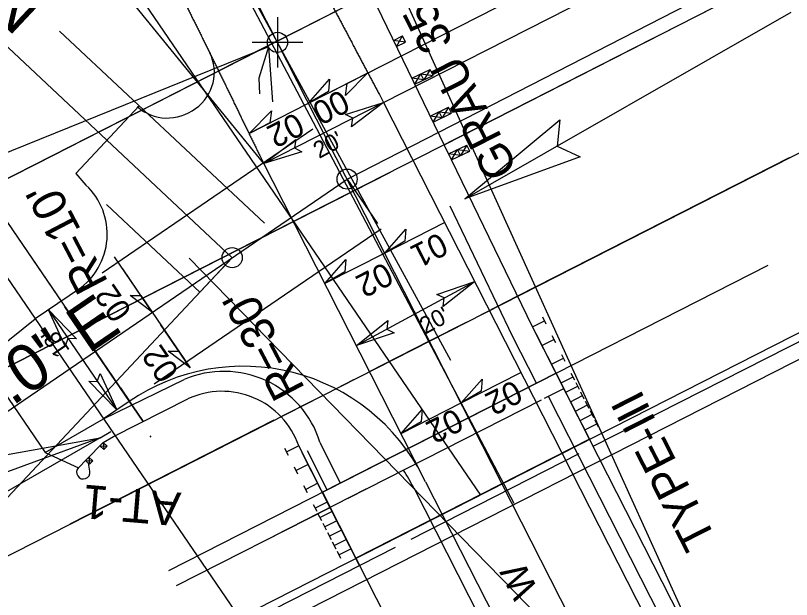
# Model space of a CAD drawing. Extents: x 557583 to 560285, y 513145 to 516544.
# Drawn here: x 559282.2 to 559397.5, y 515542.3 to 515629.1 of the extents above; entities that cross this region are included whole.
import ezdxf

# ---------------------------------------------------------------- set-up
doc = ezdxf.new("R2010")
doc.units = 0
for name, color, linetype in [('COGO Default Chain', 7, 'Continuous'), ('Exist Environmental Wetland Boundary', 7, 'Continuous'), ('Exist Environmental Wetland Boundary Cogo Point CELL', 7, 'Continuous'), ('Exist Hydro Jurisdictional Stream or Body of Water NEU Mitigable Cogo Comment', 7, 'Continuous'), ('Exist Hydro Jurisdictional Stream or Body of Water NEU Mitigable Cogo Elevation', 7, 'Continuous'), ('Exist Hydro Jurisdictional Stream or Body of Water NEU Mitigable Cogo Point CELL', 7, 'Continuous'), ('Exist Hydro Swamp or Marsh', 7, 'Continuous'), ('Prop Approach Slab', 7, 'Continuous'), ('Prop Dimension', 7, 'Continuous'), ('Prop DSN Text', 7, 'Continuous'), ('Prop EOT', 7, 'Continuous'), ('Prop Guardrail', 7, 'Continuous'), ('Prop Guardrail Anchor Unit CELL', 7, 'Continuous'), ('Prop Guardrail Shop Curved', 7, 'Continuous'), ('Prop Paved Shoulder', 7, 'Continuous'), ('Prop Roadway Bridge', 7, 'Continuous'), ('Prop SBG', 7, 'Continuous'), ('Prop Structure Anchor Unit CELL', 7, 'Continuous'), ('Prop Superelevation Label', 7, 'Continuous'), ('Prop Terminator CELL', 7, 'Continuous'), ('Scratch_Level_0', 7, 'Continuous'), ('Scratch_Level_1', 7, 'Continuous'), ('Scratch_Level_2', 7, 'Continuous'), ('Scratch_Level_3', 7, 'Continuous'), ('Scratch_Level_4', 7, 'Continuous'), ('Scratch_Level_6', 7, 'Continuous'), ('Scratch_Level_7', 7, 'Continuous'), ('Scratch_Level_8', 7, 'Continuous')]:
    doc.layers.add(name, color=color, linetype=linetype)

msp = doc.modelspace()

# ---------------------------------------------------------------- linework, layer by layer
at = {"layer": 'COGO Default Chain'}
for p, q in [((559321.14, 515628.83), (559321.14, 515621.33)), ((559324.89, 515625.08), (559317.39, 515625.08))]:
    msp.add_line(p, q, dxfattribs=at)
msp.add_arc((558429.99, 515171.37), 1000, 26.98193, 30.25241, dxfattribs=at)
at = {"layer": 'Exist Environmental Wetland Boundary'}
for p, q in [((559331.48, 515604.76), (559335.99, 515598.16)), ((559314.39, 515593.08), (559308.92, 515587.24))]:
    msp.add_line(p, q, dxfattribs=at)
at = {"layer": 'Exist Environmental Wetland Boundary Cogo Point CELL'}
for p, q in [((559331.48, 515604.76), (559390.68, 515635.1)), ((559319.8, 515624.4), (559235.59, 515590.45)), ((559313.36, 515591.99), (559124.03, 515390.09))]:
    msp.add_line(p, q, dxfattribs=at)
for centre in [(559321.14, 515625.08), (559321.14, 515625.08), (559331.48, 515604.76), (559331.48, 515604.76), (559314.39, 515593.08)]:
    msp.add_circle(centre, 1.5, dxfattribs=at)
at = {"layer": 'Exist Hydro Jurisdictional Stream or Body of Water NEU Mitigable Cogo Elevation'}
for p, q in [((559314.39, 515593.08), (559222.63, 515679.13)), ((559379.56, 515510.32), (559321.14, 515625.08)), ((559211.5, 515522.74), (559331.48, 515604.76))]:
    msp.add_line(p, q, dxfattribs=at)
msp.add_arc((558429.99, 515171.37), 1000, 26.98193, 30.25241, dxfattribs=at)
at = {"layer": 'Exist Hydro Jurisdictional Stream or Body of Water NEU Mitigable Cogo Point CELL'}
for p, q in [((559325.73, 515616.05), (559334.57, 515620.55)), ((559316.9, 515611.55), (559325.73, 515616.05)), ((559345.99, 515598.31), (559337.07, 515593.77)), ((559337.07, 515593.77), (559328.16, 515589.23)), ((559302.52, 515584.96), (559298.12, 515591.4)), ((559308.16, 515576.71), (559303.76, 515583.15)), ((559348.42, 515571.49), (559357.33, 515576.03)), ((559339.51, 515566.95), (559348.42, 515571.49))]:
    msp.add_line(p, q, dxfattribs=at)
for points in [[(559334.57, 515620.55), (559331.24, 515617.17), (559331.48, 515618.97)], [(559325.73, 515616.05), (559328.86, 515619.61), (559328.73, 515617.8)], [(559316.9, 515611.55), (559320.23, 515614.93), (559319.99, 515613.12)], [(559337.07, 515593.77), (559340.21, 515597.33), (559340.07, 515595.52)], [(559328.16, 515589.23), (559331.29, 515592.8), (559331.16, 515590.98)], [(559302.52, 515584.96), (559299.24, 515587.45), (559300.82, 515587.45)], [(559308.16, 515576.71), (559304.89, 515579.19), (559306.47, 515579.19)], [(559348.42, 515571.49), (559351.55, 515575.05), (559351.41, 515573.24)], [(559339.51, 515566.95), (559342.64, 515570.52), (559342.5, 515568.7)]]:
    msp.add_lwpolyline(points, close=True, dxfattribs=at)
at = {"layer": 'Exist Hydro Swamp or Marsh'}
for p, q in [((559321.04, 515625.26), (559316.59, 515622.99)), ((559321.04, 515625.26), (559316.59, 515622.99)), ((559294.05, 515579.18), (559291.23, 515583.3))]:
    msp.add_line(p, q, dxfattribs=at)
at = {"layer": 'Prop Approach Slab'}
for p, q in [((559362.55, 515575.91), (559327.8, 515558.21)), ((559367.54, 515566.11), (559362.55, 515575.91)), ((559332.79, 515548.41), (559367.54, 515566.11)), ((559367.01, 515561.88), (559367.01, 515561.89)), ((559327.8, 515558.21), (559332.79, 515548.41))]:
    msp.add_line(p, q, dxfattribs=at)
at = {"layer": 'Prop Dimension'}
for p, q in [((559336.91, 515616.13), (559376.42, 515636.25)), ((559325.73, 515616.05), (559358.53, 515632.75)), ((559348.99, 515601.82), (559397.5, 515629.56)), ((559332.86, 515580.01), (559350.45, 515589.53)), ((559294.76, 515566.31), (559005.69, 515460.4))]:
    msp.add_line(p, q, dxfattribs=at)
at = {"layer": 'Prop DSN Text'}
for p, q in [((559319.09, 515607.06), (559285.65, 515648.17)), ((559319.8, 515624.4), (559320.41, 515616.26)), ((559319.09, 515607.06), (559336.91, 515616.13)), ((559301.18, 515568.74), (559289.52, 515585.8)), ((559287.08, 515585.31), (559297.24, 515570.45))]:
    msp.add_line(p, q, dxfattribs=at)
msp.add_lwpolyline([(559319.8, 515624.4), (559318.35, 515619.75), (559318.47, 515617.41)], dxfattribs=at)
at = {"layer": 'Prop EOT'}
for p, q in [((559336.91, 515616.14), (559388.47, 515514.85)), ((559300.55, 515615.65), (559291.13, 515605.61)), ((559343.16, 515559.77), (559318.83, 515607.57)), ((559291.13, 515605.61), (559292.66, 515603.86)), ((559291.83, 515588.56), (559285.12, 515583.97)), ((559277.28, 515577.73), (559285.12, 515583.97)), ((559277.28, 515577.73), (559286.58, 515564.12)), ((559299.09, 515571.72), (559295.28, 515569.11)), ((559286.58, 515564.12), (559295.28, 515569.11)), ((559343.16, 515559.77), (559370.65, 515505.78))]:
    msp.add_line(p, q, dxfattribs=at)
for centre, radius, start, end in [((559285.82, 515596.57), 10, 304.3572, 46.838), ((559316.02, 515546.95), 30, 26.9819, 124.3572)]:
    msp.add_arc(centre, radius, start, end, dxfattribs=at)
msp.add_ellipse((559305, 515620.4), major_axis=(6.07, 3.09), ratio=0.953938, start_param=3.488147, end_param=6.286388, dxfattribs=at)
for points in [[(559312.79, 515660.31), (559313.13, 515659.72), (559313.47, 515659.13), (559313.81, 515658.54), (559314.15, 515657.95), (559314.49, 515657.35), (559314.83, 515656.76), (559315.16, 515656.17), (559315.5, 515655.58), (559315.84, 515654.98), (559316.17, 515654.39), (559316.51, 515653.8), (559316.85, 515653.2), (559317.18, 515652.61), (559317.52, 515652.02), (559317.85, 515651.42), (559318.18, 515650.83), (559318.52, 515650.23), (559318.85, 515649.64), (559319.18, 515649.04), (559319.52, 515648.44), (559319.85, 515647.85), (559320.18, 515647.25), (559320.51, 515646.66), (559320.84, 515646.06), (559321.17, 515645.46), (559321.5, 515644.87), (559321.83, 515644.27), (559322.16, 515643.67), (559322.49, 515643.07), (559322.82, 515642.48), (559323.15, 515641.88), (559323.48, 515641.28), (559323.8, 515640.68), (559324.13, 515640.08), (559324.46, 515639.48), (559324.78, 515638.88), (559325.11, 515638.28), (559325.43, 515637.69), (559325.76, 515637.09), (559326.08, 515636.49), (559326.41, 515635.88), (559326.73, 515635.28), (559327.05, 515634.68), (559327.38, 515634.08), (559327.7, 515633.48), (559328.02, 515632.88), (559328.34, 515632.28), (559328.66, 515631.68), (559328.99, 515631.07), (559329.31, 515630.47), (559329.63, 515629.87), (559329.94, 515629.27), (559330.26, 515628.67), (559330.58, 515628.07), (559330.89, 515627.48), (559331.21, 515626.88), (559331.53, 515626.28), (559331.84, 515625.69), (559332.16, 515625.09), (559332.48, 515624.49), (559332.79, 515623.89), (559333.11, 515623.3), (559333.43, 515622.7), (559333.74, 515622.1), (559334.06, 515621.51), (559334.38, 515620.91), (559334.69, 515620.31), (559335.01, 515619.72), (559335.33, 515619.12), (559335.64, 515618.52), (559335.96, 515617.92), (559336.28, 515617.33), (559336.91, 515616.13)], [(559296.77, 515651.44), (559297.09, 515650.85), (559297.4, 515650.26), (559297.72, 515649.67), (559298.03, 515649.07), (559298.34, 515648.48), (559298.65, 515647.89), (559298.96, 515647.3), (559299.28, 515646.7), (559299.59, 515646.11), (559299.9, 515645.52), (559300.21, 515644.92), (559300.52, 515644.33), (559300.83, 515643.74), (559301.13, 515643.14), (559301.44, 515642.55), (559301.75, 515641.95), (559302.06, 515641.36), (559302.37, 515640.77), (559302.67, 515640.17), (559302.98, 515639.58), (559303.28, 515638.98), (559303.59, 515638.38), (559303.9, 515637.79), (559304.2, 515637.19), (559304.5, 515636.6), (559304.81, 515636), (559305.11, 515635.4), (559305.42, 515634.81), (559305.72, 515634.21), (559306.02, 515633.61), (559306.32, 515633.01), (559306.62, 515632.42), (559306.92, 515631.82), (559307.23, 515631.22), (559307.53, 515630.62), (559307.83, 515630.02), (559308.13, 515629.43), (559308.42, 515628.83), (559308.72, 515628.23), (559309.02, 515627.63), (559309.32, 515627.03), (559309.62, 515626.43), (559309.91, 515625.83), (559310.21, 515625.23), (559310.51, 515624.63), (559310.8, 515624.03), (559311.1, 515623.43), (559311.39, 515622.83), (559311.69, 515622.23), (559311.98, 515621.63), (559312.27, 515621.03), (559312.57, 515620.42), (559312.87, 515619.81), (559313.16, 515619.21), (559313.46, 515618.6), (559313.75, 515617.99), (559314.05, 515617.38), (559314.35, 515616.78), (559314.64, 515616.17), (559314.94, 515615.56), (559315.24, 515614.96), (559315.53, 515614.35), (559315.83, 515613.74), (559316.12, 515613.13), (559316.42, 515612.53), (559316.72, 515611.92), (559317.01, 515611.31), (559317.31, 515610.7), (559317.61, 515610.1), (559317.9, 515609.49), (559318.2, 515608.88), (559318.49, 515608.27), (559319.09, 515607.06)]]:
    msp.add_spline(points, degree=3, dxfattribs=at)
at = {"layer": 'Prop Guardrail'}
for p, q in [((559359.04, 515582.82), (559346.98, 515607.6)), ((559296.77, 515566.51), (559307.8, 515572.09)), ((559295.23, 515565.62), (559296.77, 515566.51))]:
    msp.add_line(p, q, dxfattribs=at)
at = {"layer": 'Prop Guardrail Anchor Unit CELL'}
for p, q in [((559335.87, 515630.55), (559346.76, 515608.05)), ((559338.37, 515625.37), (559339.74, 515626.03)), ((559338.81, 515624.47), (559338.37, 515625.37)), ((559340.17, 515625.13), (559338.37, 515625.37)), ((559338.81, 515624.47), (559339.74, 515626.03)), ((559338.81, 515624.47), (559340.17, 515625.13)), ((559340.17, 515625.13), (559339.74, 515626.03)), ((559341.1, 515619.75), (559343.83, 515621.07)), ((559341.53, 515618.85), (559342.46, 515620.41)), ((559342.9, 515619.51), (559342.46, 515620.41)), ((559342.46, 515620.41), (559344.26, 515620.17)), ((559343.83, 515621.07), (559342.9, 515619.51)), ((559344.26, 515620.17), (559343.83, 515621.07)), ((559341.53, 515618.85), (559341.1, 515619.75)), ((559342.9, 515619.51), (559341.1, 515619.75)), ((559341.53, 515618.85), (559344.26, 515620.17)), ((559343.82, 515614.12), (559346.55, 515615.45)), ((559344.26, 515613.22), (559345.19, 515614.78)), ((559345.62, 515613.88), (559345.19, 515614.78)), ((559345.19, 515614.78), (559346.99, 515614.54)), ((559346.55, 515615.45), (559345.62, 515613.88)), ((559346.99, 515614.54), (559346.55, 515615.45)), ((559344.26, 515613.22), (559343.82, 515614.12)), ((559345.62, 515613.88), (559343.82, 515614.12)), ((559344.26, 515613.22), (559346.99, 515614.54)), ((559346.54, 515608.5), (559349.28, 515609.82)), ((559346.98, 515607.6), (559347.91, 515609.16)), ((559346.98, 515607.6), (559349.71, 515608.92)), ((559348.35, 515608.26), (559347.91, 515609.16)), ((559347.91, 515609.16), (559349.71, 515608.92)), ((559349.28, 515609.82), (559348.35, 515608.26)), ((559349.71, 515608.92), (559349.28, 515609.82)), ((559346.98, 515607.6), (559346.54, 515608.5)), ((559348.35, 515608.26), (559346.54, 515608.5)), ((559295.23, 515565.62), (559292.74, 515563.1)), ((559295.23, 515565.62), (559294.74, 515565.13)), ((559294.74, 515565.13), (559295.31, 515564.56)), ((559294.74, 515565.13), (559295.8, 515565.06)), ((559295.8, 515565.06), (559295.23, 515565.62)), ((559295.23, 515565.62), (559295.31, 515564.56)), ((559295.31, 515564.56), (559295.8, 515565.06)), ((559292.74, 515563.1), (559291.54, 515561.87)), ((559293.09, 515563.45), (559292.6, 515562.96)), ((559292.6, 515562.96), (559292.85, 515562.71)), ((559292.6, 515562.96), (559292.85, 515562.71)), ((559292.6, 515562.96), (559293.18, 515562.39)), ((559292.6, 515562.96), (559293.67, 515562.89)), ((559292.69, 515563.05), (559292.79, 515563.14)), ((559292.69, 515563.05), (559292.79, 515563.14)), ((559293.67, 515562.89), (559293.09, 515563.45)), ((559293.09, 515563.45), (559293.18, 515562.39)), ((559293.18, 515562.39), (559293.67, 515562.89)), ((559293.22, 515561.33), (559293.04, 515562.52))]:
    msp.add_line(p, q, dxfattribs=at)
msp.add_ellipse((559292.25, 515561.18), major_axis=(0.708, -0.696), ratio=0.995379, start_param=3.141593, end_param=7.214552, dxfattribs=at)
at = {"layer": 'Prop Guardrail Shop Curved'}
msp.add_arc((559312.89, 515561.16), 12.06, 19.1719, 114.9774, dxfattribs=at)
at = {"layer": 'Prop Paved Shoulder'}
msp.add_line((559286.58, 515564.12), (559291.54, 515561.87), dxfattribs=at)
at = {"layer": 'Prop Roadway Bridge'}
for p, q in [((559367.54, 515566.11), (559332.79, 515548.41)), ((559413.87, 515475.12), (559367.54, 515566.11)), ((559332.79, 515548.41), (559379.11, 515457.43))]:
    msp.add_line(p, q, dxfattribs=at)
at = {"layer": 'Prop SBG'}
for p, q in [((559356.14, 515581.3), (559346.78, 515600.74)), ((559359.64, 515574.43), (559356.14, 515581.3)), ((559295.28, 515569.11), (559307.25, 515574.97)), ((559294.76, 515566.31), (559296.36, 515567.23)), ((559327.44, 515565.68), (559330.45, 515559.56)), ((559328.54, 515558.59), (559325.59, 515564.37))]:
    msp.add_line(p, q, dxfattribs=at)
msp.add_arc((559313.15, 515561.2), 14.98, 17.3827, 113.1882, dxfattribs=at)
at = {"layer": 'Prop Structure Anchor Unit CELL'}
for p, q in [((559359.04, 515582.82), (559360.82, 515583.72)), ((559361.08, 515583.21), (559360.56, 515584.23)), ((559367.54, 515566.11), (559359.04, 515582.82)), ((559362.5, 515580.43), (559361.98, 515581.45)), ((559360.45, 515580.03), (559362.24, 515580.94)), ((559361.87, 515577.25), (559363.65, 515578.15)), ((559363.91, 515577.64), (559363.39, 515578.66)), ((559363.29, 515574.46), (559365.07, 515575.37)), ((559365.33, 515574.86), (559364.81, 515575.88)), ((559366.04, 515573.47), (559365.52, 515574.49)), ((559364, 515573.07), (559365.78, 515573.98)), ((559366.75, 515572.07), (559366.23, 515573.09)), ((559364.71, 515571.68), (559366.49, 515572.58)), ((559365.42, 515570.28), (559367.2, 515571.19)), ((559367.46, 515570.68), (559366.94, 515571.7)), ((559366.12, 515568.89), (559367.91, 515569.8)), ((559368.17, 515569.29), (559367.65, 515570.31)), ((559366.83, 515567.5), (559368.62, 515568.41)), ((559368.88, 515567.9), (559368.36, 515568.92)), ((559324.28, 515565.12), (559322.5, 515564.21)), ((559332.79, 515548.41), (559324.28, 515565.12)), ((559322.76, 515563.7), (559322.24, 515564.72)), ((559324.18, 515560.92), (559323.66, 515561.94)), ((559325.7, 515562.34), (559323.92, 515561.43)), ((559327.12, 515559.55), (559325.33, 515558.64)), ((559325.59, 515558.13), (559325.07, 515559.15)), ((559327.01, 515555.35), (559326.49, 515556.37)), ((559328.53, 515556.77), (559326.75, 515555.86)), ((559327.72, 515553.96), (559327.2, 515554.98)), ((559329.24, 515555.37), (559327.46, 515554.47)), ((559328.43, 515552.56), (559327.91, 515553.58)), ((559329.95, 515553.98), (559328.17, 515553.07)), ((559330.66, 515552.59), (559328.88, 515551.68)), ((559329.14, 515551.17), (559328.62, 515552.19)), ((559331.37, 515551.2), (559329.59, 515550.29)), ((559329.85, 515549.78), (559329.33, 515550.8)), ((559330.56, 515548.39), (559330.04, 515549.41)), ((559332.08, 515549.8), (559330.3, 515548.9))]:
    msp.add_line(p, q, dxfattribs=at)
at = {"layer": 'Prop Superelevation Label'}
for q in [(559296.88, 515593.22), (559308.16, 515576.71)]:
    msp.add_line((559302.52, 515584.96), q, dxfattribs=at)
at = {"layer": 'Prop Terminator CELL'}
for points in [[(559331.24, 515614.37), (559336.91, 515616.13), (559332.14, 515612.53), (559332.34, 515613.8)], [(559366.15, 515608.06), (559348.99, 515601.82), (559363.11, 515613.58), (559362.7, 515609.66)], [(559324.76, 515608.82), (559319.09, 515607.06), (559323.85, 515610.66), (559323.66, 515609.39)], [(559344.82, 515587.63), (559350.45, 515589.53), (559345.77, 515585.82), (559345.93, 515587.09)], [(559289.55, 515579.91), (559287.08, 515585.31), (559291.26, 515581.04), (559289.98, 515581.07)], [(559338.48, 515581.91), (559332.86, 515580.01), (559337.54, 515583.73), (559337.37, 515582.46)], [(559294.77, 515575.85), (559297.24, 515570.45), (559293.06, 515574.72), (559294.34, 515574.69)], [(559276.78, 515563.09), (559294.76, 515566.31), (559278.83, 515557.13), (559279.9, 515560.92)]]:
    msp.add_lwpolyline(points, close=True, dxfattribs=at)
at = {"layer": 'Scratch_Level_0'}
for p, q in [((559361.38, 515572.48), (559390.26, 515515.76)), ((559341.38, 515558.86), (559368.87, 515504.87))]:
    msp.add_line(p, q, dxfattribs=at)
msp.add_arc((559316.43, 515546.16), 28, 26.9819, 33.2638, dxfattribs=at)
at = {"layer": 'Scratch_Level_1'}
for p, q in [((559374.51, 515652.49), (559267.58, 515598.02)), ((559346, 515609.91), (559385.85, 515630.2)), ((559397.2, 515607.92), (559356.89, 515587.4)), ((559278.92, 515575.76), (559337.93, 515605.8)), ((559368.08, 515565.05), (559408.54, 515585.64)), ((559302.66, 515529.12), (559409.6, 515583.57)), ((559320.61, 515568.93), (559290.26, 515553.48)), ((559341.03, 515551.27), (559365.98, 515563.98)), ((559334.29, 515558.69), (559320.57, 515551.71)), ((559301.6, 515531.2), (559338.67, 515550.07))]:
    msp.add_line(p, q, dxfattribs=at)
at = {"layer": 'Scratch_Level_2'}
for p, q in [((559098.28, 515511.79), (559543.81, 515738.73)), ((559555.17, 515716.41), (559109.6, 515489.55)), ((559120.94, 515467.27), (559566.52, 515694.13))]:
    msp.add_line(p, q, dxfattribs=at)
at = {"layer": 'Scratch_Level_3'}
for p, q in [((559222.63, 515679.13), (559314.39, 515593.08)), ((559293.8, 515675.18), (559356.28, 515556.58)), ((559293.8, 515675.18), (559346.84, 515577.85)), ((559319.18, 515598.19), (559288.72, 515626.75)), ((559261.98, 515617.82), (559318.42, 515535.27)), ((559326.4, 515612.19), (559295.07, 515590.77)), ((559211.5, 515522.74), (559331.48, 515604.76)), ((559309.6, 515587.97), (559295.73, 515600.98)), ((559336.56, 515597.33), (559302.82, 515574.27)), ((559587.3, 515306.64), (559308.02, 515593)), ((559302.28, 515566.61), (559302.14, 515566.42))]:
    msp.add_line(p, q, dxfattribs=at)
at = {"layer": 'Scratch_Level_4'}
for p, q in [((559351.37, 515557.79), (559294.93, 515640.35)), ((559321.04, 515625.26), (559335.05, 515632.39)), ((559260.19, 515628.71), (559288.97, 515586.61)), ((559376.94, 515625.66), (559346, 515609.91)), ((559265.83, 515620.45), (559301.18, 515568.74)), ((559350.61, 515584.2), (559356.86, 515587.39)), ((559290.16, 515584.87), (559297.56, 515574.05)), ((559343.73, 515580.7), (559349.23, 515583.5)), ((559368.08, 515565.05), (559359.57, 515581.75)), ((559334.82, 515576.16), (559343.73, 515580.7)), ((559329.8, 515573.61), (559332.5, 515574.98)), ((559297.78, 515573.72), (559299.13, 515571.75)), ((559360.81, 515572.19), (559363.69, 515573.66)), ((559321.58, 515569.42), (559326.96, 515572.16)), ((559331.66, 515557.35), (559360.36, 515571.97)), ((559299.17, 515558.01), (559319.06, 515568.14)), ((559333.33, 515547.35), (559324.82, 515564.06)), ((559306.13, 515544.35), (559328.94, 515555.97))]:
    msp.add_line(p, q, dxfattribs=at)
at = {"layer": 'Scratch_Level_6'}
for p, q in [((559265.42, 515514.11), (559443.65, 515604.85)), ((559304.98, 515546.6), (559394.1, 515591.97))]:
    msp.add_line(p, q, dxfattribs=at)
at = {"layer": 'Scratch_Level_7'}
for p, q in [((559312.37, 515620.84), (559323.76, 515626.64)), ((559285.4, 515607.1), (559310.8, 515620.04))]:
    msp.add_line(p, q, dxfattribs=at)
at = {"layer": 'Scratch_Level_8'}
msp.add_line((559428.04, 515437.39), (559305.09, 515708.93), dxfattribs=at)

# ---------------------------------------------------------------- texts
at = {"layer": 'Exist Hydro Jurisdictional Stream or Body of Water NEU Mitigable Cogo Comment'}
for s, height, rotation, p in [('N 46%%d 50\' 16.8" W', 7, 136.838, (559287.02, 515630.95)), ('N 55%%d 38\' 34.0" E', 7, 34.3572, (559239.3, 515541.99)), ('N 26%%d 58\' 54.9" W', 4, 116.9819, (559376.82, 515510.54))]:
    msp.add_text(s, height=height, rotation=rotation, dxfattribs=at).set_placement(p)
at = {"layer": 'Prop Dimension'}
for s, p in [("R=10'", (559296.05, 515589.43)), ("R=30'", (559325.28, 515573.61))]:
    msp.add_text(s, height=5, rotation=117.5992, dxfattribs=at).set_placement(p)
at = {"layer": 'Prop DSN Text'}
for s, rotation, p in [("20'", 28.4259, (559327.32, 515607.74)), ("20'", 28.4259, (559343.12, 515581.66)), ("18'", 124.3572, (559290.34, 515579.31))]:
    msp.add_text(s, height=2.5, rotation=rotation, dxfattribs=at).set_placement(p)
at = {"layer": 'Prop Guardrail Anchor Unit CELL'}
for s, rotation, p in [('GRAU 350 TL-2', 116.9819, (559356.96, 515606.27)), ('AT-1', 175.1848, (559306.88, 515558.14))]:
    msp.add_text(s, height=5, rotation=rotation, dxfattribs=at).set_placement(p)
at = {"layer": 'Prop Structure Anchor Unit CELL'}
msp.add_text('TYPE-III', height=5, rotation=116.9819, dxfattribs=at).set_placement((559386.45, 515551.22))
at = {"layer": 'Prop Superelevation Label'}
for s, rotation, p in [('00', 206.9819, (559330.62, 515618.15)), ('02', 206.9819, (559323.89, 515614.75)), ('01', 206.9819, (559345.23, 515596.93)), ('02', 206.9819, (559337.1, 515592.5)), ('02', 124.3572, (559299.59, 515585.12)), ('02', 124.3572, (559306.62, 515576.14)), ('02', 206.9819, (559356.32, 515575)), ('02', 206.9819, (559347.52, 515570.8))]:
    msp.add_text(s, height=3.5, rotation=rotation, dxfattribs=at).set_placement(p)

doc.saveas('drawing.dxf')
